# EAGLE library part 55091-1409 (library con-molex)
0.635 mm PITCH B TO B CONN. Source: http://www.molex.com/pdm_docs/sd/550911609_sd.pdf
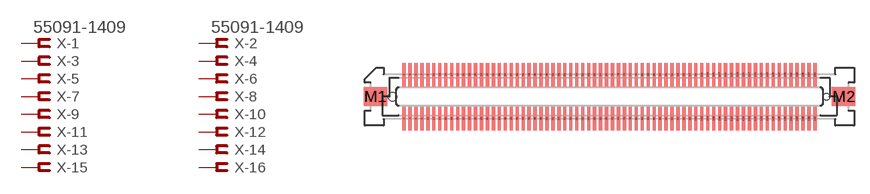
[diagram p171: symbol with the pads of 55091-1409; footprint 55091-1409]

Designator prefix X; gates -1=FV -2=FV -3=F -4=F -5=F -6=F -7=F -8=F -9=F -10=F -11=F -12=F -13=F -14=F -15=F -16=F -17=F -18=F -19=F -20=F -21=F -22=F -23=F -24=F -25=F -26=F -27=F -28=F -29=F -30=F -31=F -32=F -33=F -34=F -35=F -36=F -37=F -38=F -39=F -40=F -41=F -42=F -43=F -44=F -45=F -46=F -47=F -48=F -49=F -50=F -51=F -52=F -53=F -54=F -55=F -56=F -57=F -58=F -59=F -60=F -61=F -62=F -63=F -64=F -65=F -66=F -67=F -68=F -69=F -70=F -71=F -72=F -73=F -74=F -75=F -76=F -77=F -78=F -79=F -80=F -81=F -82=F -83=F -84=F -85=F -86=F -87=F -88=F -89=F -90=F -91=F -92=F -93=F -94=F -95=F -96=F -97=F -98=F -99=F -100=F -101=F -102=F -103=F -104=F -105=F -106=F -107=F -108=F -109=F -110=F -111=F -112=F -113=F -114=F -115=F -116=F -117=F -118=F -119=F -120=F -121=F -122=F -123=F -124=F -125=F -126=F -127=F -128=F -129=F -130=F -131=F -132=F -133=F -134=F -135=F -136=F -137=F -138=F -139=F -140=F

## 55091-1409 (OC_FARNELL: unknown; OC_NEWARK: unknown)  [55091-1409]
1  -1:S  pas
2  -2:S  pas
3  -3:S  pas
4  -4:S  pas
5  -5:S  pas
6  -6:S  pas
7  -7:S  pas
8  -8:S  pas
9  -9:S  pas
10  -10:S  pas
11  -11:S  pas
12  -12:S  pas
13  -13:S  pas
14  -14:S  pas
15  -15:S  pas
16  -16:S  pas
17  -17:S  pas
18  -18:S  pas
19  -19:S  pas
20  -20:S  pas
21  -21:S  pas
22  -22:S  pas
23  -23:S  pas
24  -24:S  pas
25  -25:S  pas
26  -26:S  pas
27  -27:S  pas
28  -28:S  pas
29  -29:S  pas
30  -30:S  pas
31  -31:S  pas
32  -32:S  pas
33  -33:S  pas
34  -34:S  pas
35  -35:S  pas
36  -36:S  pas
37  -37:S  pas
38  -38:S  pas
39  -39:S  pas
40  -40:S  pas
41  -41:S  pas
42  -42:S  pas
43  -43:S  pas
44  -44:S  pas
45  -45:S  pas
46  -46:S  pas
47  -47:S  pas
48  -48:S  pas
49  -49:S  pas
50  -50:S  pas
51  -51:S  pas
52  -52:S  pas
53  -53:S  pas
54  -54:S  pas
55  -55:S  pas
56  -56:S  pas
57  -57:S  pas
58  -58:S  pas
59  -59:S  pas
60  -60:S  pas
61  -61:S  pas
62  -62:S  pas
63  -63:S  pas
64  -64:S  pas
65  -65:S  pas
66  -66:S  pas
67  -67:S  pas
68  -68:S  pas
69  -69:S  pas
70  -70:S  pas
71  -71:S  pas
72  -72:S  pas
73  -73:S  pas
74  -74:S  pas
75  -75:S  pas
76  -76:S  pas
77  -77:S  pas
78  -78:S  pas
79  -79:S  pas
80  -80:S  pas
81  -81:S  pas
82  -82:S  pas
83  -83:S  pas
84  -84:S  pas
85  -85:S  pas
86  -86:S  pas
87  -87:S  pas
88  -88:S  pas
89  -89:S  pas
90  -90:S  pas
91  -91:S  pas
92  -92:S  pas
93  -93:S  pas
94  -94:S  pas
95  -95:S  pas
96  -96:S  pas
97  -97:S  pas
98  -98:S  pas
99  -99:S  pas
100  -100:S  pas
101  -101:S  pas
102  -102:S  pas
103  -103:S  pas
104  -104:S  pas
105  -105:S  pas
106  -106:S  pas
107  -107:S  pas
108  -108:S  pas
109  -109:S  pas
110  -110:S  pas
111  -111:S  pas
112  -112:S  pas
113  -113:S  pas
114  -114:S  pas
115  -115:S  pas
116  -116:S  pas
117  -117:S  pas
118  -118:S  pas
119  -119:S  pas
120  -120:S  pas
121  -121:S  pas
122  -122:S  pas
123  -123:S  pas
124  -124:S  pas
125  -125:S  pas
126  -126:S  pas
127  -127:S  pas
128  -128:S  pas
129  -129:S  pas
130  -130:S  pas
131  -131:S  pas
132  -132:S  pas
133  -133:S  pas
134  -134:S  pas
135  -135:S  pas
136  -136:S  pas
137  -137:S  pas
138  -138:S  pas
139  -139:S  pas
140  -140:S  pas

## Footprint 55091-1409 (pad centres in mm)
0.635 mm PITCH B TO B CONN. Source: http://www.molex.com/pdm_docs/sd/550911609_sd.pdf
smd 0.35 x 2.5: 1 -21.907,2.35; 2 -21.907,-2.35; 3 -21.273,2.35; 4 -21.273,-2.35; 5 -20.637,2.35; 6 -20.637,-2.35; 7 -20.003,2.35; 8 -20.003,-2.35; 9 -19.367,2.35; 10 -19.367,-2.35; 11 -18.733,2.35; 12 -18.733,-2.35; 13 -18.098,2.35; 14 -18.098,-2.35; 15 -17.462,2.35; 16 -17.462,-2.35; 17 -16.828,2.35; 18 -16.828,-2.35; 19 -16.192,2.35; 20 -16.192,-2.35; 21 -15.557,2.35; 22 -15.557,-2.35; 23 -14.922,2.35; 24 -14.922,-2.35; 25 -14.287,2.35; 26 -14.287,-2.35; 27 -13.652,2.35; 28 -13.652,-2.35; 29 -13.018,2.35; 30 -13.018,-2.35; 31 -12.383,2.35; 32 -12.383,-2.35; 33 -11.748,2.35; 34 -11.748,-2.35; 35 -11.113,2.35; 36 -11.113,-2.35; 37 -10.477,2.35; 38 -10.477,-2.35; 39 -9.842,2.35; 40 -9.842,-2.35; 41 -9.207,2.35; 42 -9.207,-2.35; 43 -8.572,2.35; 44 -8.572,-2.35; 45 -7.938,2.35; 46 -7.938,-2.35; 47 -7.303,2.35; 48 -7.303,-2.35; 49 -6.668,2.35; 50 -6.668,-2.35; 51 -6.032,2.35; 52 -6.032,-2.35; 53 -5.397,2.35; 54 -5.397,-2.35; 55 -4.763,2.35; 56 -4.763,-2.35; 57 -4.128,2.35; 58 -4.128,-2.35; 59 -3.493,2.35; 60 -3.493,-2.35; 61 -2.857,2.35; 62 -2.857,-2.35; 63 -2.223,2.35; 64 -2.223,-2.35; 65 -1.587,2.35; 66 -1.587,-2.35; 67 -0.953,2.35; 68 -0.953,-2.35; 69 -0.318,2.35; 70 -0.318,-2.35; 71 0.318,2.35; 72 0.318,-2.35; 73 0.953,2.35; 74 0.953,-2.35; 75 1.587,2.35; 76 1.587,-2.35; 77 2.223,2.35; 78 2.223,-2.35; 79 2.857,2.35; 80 2.857,-2.35; 81 3.493,2.35; 82 3.493,-2.35; 83 4.128,2.35; 84 4.128,-2.35; 85 4.763,2.35; 86 4.763,-2.35; 87 5.397,2.35; 88 5.397,-2.35; 89 6.032,2.35; 90 6.032,-2.35; 91 6.668,2.35; 92 6.668,-2.35; 93 7.303,2.35; 94 7.303,-2.35; 95 7.938,2.35; 96 7.938,-2.35; 97 8.572,2.35; 98 8.572,-2.35; 99 9.207,2.35; 100 9.207,-2.35; 101 9.842,2.35; 102 9.842,-2.35; 103 10.477,2.35; 104 10.477,-2.35; 105 11.113,2.35; 106 11.113,-2.35; 107 11.748,2.35; 108 11.748,-2.35; 109 12.383,2.35; 110 12.383,-2.35; 111 13.018,2.35; 112 13.018,-2.35; 113 13.652,2.35; 114 13.652,-2.35; 115 14.287,2.35; 116 14.287,-2.35; 117 14.922,2.35; 118 14.922,-2.35; 119 15.557,2.35; 120 15.557,-2.35; 121 16.192,2.35; 122 16.192,-2.35; 123 16.828,2.35; 124 16.828,-2.35; 125 17.462,2.35; 126 17.462,-2.35; 127 18.098,2.35; 128 18.098,-2.35; 129 18.733,2.35; 130 18.733,-2.35; 131 19.367,2.35; 132 19.367,-2.35; 133 20.003,2.35; 134 20.003,-2.35; 135 20.637,2.35; 136 20.637,-2.35; 137 21.273,2.35; 138 21.273,-2.35; 139 21.907,2.35; 140 21.907,-2.35
smd 2.5 x 2: M1 -24.975,0; M2 24.975,0
hole 0.9 at -23.16,0
hole 0.7 at 23.16,0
